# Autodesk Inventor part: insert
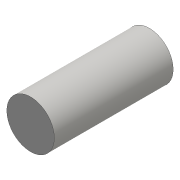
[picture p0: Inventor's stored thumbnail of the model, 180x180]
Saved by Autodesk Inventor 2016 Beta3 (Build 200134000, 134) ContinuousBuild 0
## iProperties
Created: 2016-03
Part Number: insert
Material: Generic
Document SubType Name: Modeling
Designer: Gaurav
Density: 1 g/cm^3
Appearance: Default
Author: Gaurav
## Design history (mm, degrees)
sketch "Sketch1"
  geometry: C1 r 5 at (0, 0); 1 further point
  constraints: 1 centre point, 1 coincident
  dimensions: "d0" = 10 diameter of C1
extrude "Extrusion1" new body sketch "Sketch1" distance "d1" = 25; taper "d2" = 0 deg
body "Solid1"
